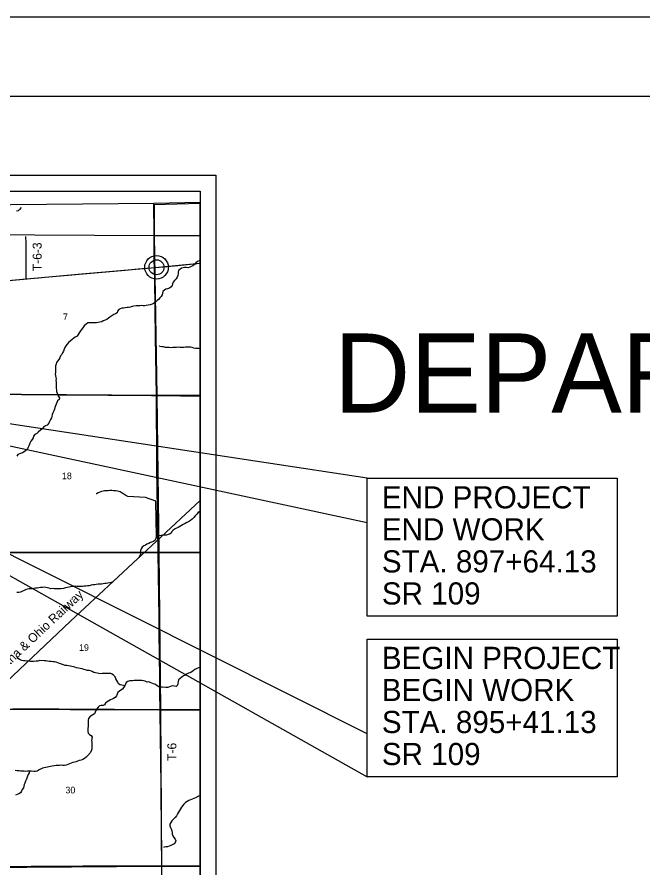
# Model space of a CAD drawing. Extents: x 0 to 34, y 0 to 22.
# Drawn here: x 7.74 to 11.7, y 16.62 to 22 of the extents above; entities that cross this region are included whole.
import ezdxf

# ---------------------------------------------------------------- set-up
doc = ezdxf.new("R2010")
doc.units = 0
for name, color, linetype in [('Default', 7, 'Continuous'), ('GM_X_County_Road', 7, 'Continuous'), ('GM_X_Minor_River', 7, 'Continuous'), ('GM_X_Rail_Line', 7, 'Continuous'), ('GM_X_Rail_Line_Text', 7, 'Continuous'), ('GM_X_Section', 7, 'Continuous'), ('GM_X_Section_Text', 7, 'Continuous'), ('GM_X_State_Route', 7, 'Continuous'), ('GM_X_Township_Road', 7, 'Continuous'), ('GM_X_Township_Road_Text', 7, 'Continuous'), ('GM_X_Unincorporated', 7, 'Continuous'), ('GM_X_Unincorporated_Location', 7, 'Continuous'), ('GM_X_US_Route', 7, 'Continuous'), ('SH_Border', 7, 'Continuous'), ('SH_Cut_Line', 7, 'Continuous'), ('SH_Data', 7, 'Continuous'), ('SH_Text', 7, 'Continuous')]:
    doc.layers.add(name, color=color, linetype=linetype)

msp = doc.modelspace()

# ---------------------------------------------------------------- linework, layer by layer
at = {"layer": 'Default'}
for points in [[(7.6731, 16.6285), (7.8317, 16.6301), (7.9032, 16.6305), (7.9964, 16.6311), (8.0835, 16.6316), (8.1582, 16.6322), (8.295, 16.6324), (8.3852, 16.6328), (8.438, 16.6333), (8.4971, 16.6335), (8.6215, 16.6337), (8.659, 16.6337), (8.7801, 16.6339), (8.9, 16.6342), (8.9, 20.8277), (8.6079, 20.8216), (7.476, 20.811)], [(7.5225, 14.1), (8.9, 14.1), (8.9, 16.6342), (8.7801, 16.6339), (8.659, 16.6337), (8.6215, 16.6337), (8.4971, 16.6335), (8.438, 16.6333), (8.3852, 16.6328), (8.295, 16.6324), (8.1582, 16.6322), (8.0835, 16.6316), (7.9964, 16.6311), (7.9032, 16.6305), (7.8317, 16.6301), (7.6731, 16.6285)]]:
    msp.add_lwpolyline(points, dxfattribs=at)
for points in [[(8.9, 20.618), (8.9, 20.8219), (8.6093, 20.8138), (8.611, 20.6193)], [(8.9, 19.6068), (8.9, 20.618), (8.611, 20.6193), (8.626, 19.6083)], [(8.9, 18.6163), (8.9, 19.6068), (8.626, 19.6083), (8.6395, 18.6159)], [(8.9, 17.622), (8.9, 18.6163), (8.6395, 18.6159), (8.6491, 17.6213)], [(8.9, 16.634), (8.9, 17.622), (8.6491, 17.6213), (8.6573, 16.6339)], [(8.9, 15.6272), (8.9, 16.634), (8.6573, 16.6339), (8.6614, 15.6262)]]:
    msp.add_lwpolyline(points, close=True, dxfattribs=at)
at = {"layer": 'GM_X_County_Road'}
for points in [[(7.4828, 19.6185), (7.4963, 19.6184), (7.5305, 19.6182), (7.7233, 19.6156), (8.0063, 19.6119), (8.056, 19.6111), (8.3201, 19.6098), (8.5938, 19.6077), (8.624, 19.6074)], [(8.624, 19.6074), (8.7772, 19.6056), (8.9, 19.6044)], [(7.4927, 18.6157), (7.5027, 18.6158), (7.5276, 18.6159), (7.935, 18.6156), (8.1215, 18.6157), (8.2739, 18.615), (8.5444, 18.6148), (8.6355, 18.6158)], [(8.6355, 18.6158), (8.6502, 18.6159), (8.9, 18.6177)], [(7.5136, 16.6249), (7.5156, 16.6255), (7.5177, 16.626), (7.5199, 16.6263), (7.5219, 16.6265), (7.5235, 16.6265), (7.5365, 16.6268), (7.5769, 16.6271), (7.6733, 16.628), (7.8319, 16.6295), (7.9034, 16.63), (7.9967, 16.6306), (8.0838, 16.6311), (8.1584, 16.6316), (8.2952, 16.6318), (8.3854, 16.6323), (8.4383, 16.6327), (8.4973, 16.6329), (8.6217, 16.6331), (8.6592, 16.6332)], [(8.6592, 16.6332), (8.7803, 16.6333), (8.9, 16.6336)]]:
    msp.add_lwpolyline(points, dxfattribs=at)
at = {"layer": 'GM_X_Minor_River'}
for points in [[(7.77, 20.7966), (7.7587, 20.7831), (7.7491, 20.776), (7.7396, 20.7719)], [(8.9, 20.4604), (8.8936, 20.4582), (8.8841, 20.4545), (8.8734, 20.4467), (8.8649, 20.4365), (8.8542, 20.4272), (8.8447, 20.4223), (8.8352, 20.419), (8.8253, 20.4149), (8.8124, 20.4162), (8.8026, 20.4171), (8.793, 20.4138), (8.7832, 20.4116), (8.7725, 20.4045), (8.7629, 20.3974), (8.7609, 20.3875), (8.7608, 20.3781), (8.7587, 20.3667), (8.7548, 20.3561), (8.7501, 20.3459), (8.739, 20.3347), (8.7305, 20.3238), (8.7262, 20.3139), (8.7238, 20.3034), (8.718, 20.2936), (8.7061, 20.2853), (8.6947, 20.2817), (8.6845, 20.2791), (8.6745, 20.2739), (8.6646, 20.2653), (8.6626, 20.2551), (8.6602, 20.2448), (8.6547, 20.2343), (8.6466, 20.2245), (8.6382, 20.2147), (8.6282, 20.2073), (8.6179, 20.1979), (8.6068, 20.1893), (8.5969, 20.1841), (8.5843, 20.18), (8.5729, 20.1782), (8.5604, 20.1757), (8.5509, 20.1747), (8.5407, 20.1744), (8.5308, 20.1757), (8.5187, 20.1754), (8.5073, 20.1755), (8.4952, 20.1738), (8.4815, 20.1716), (8.4712, 20.1695), (8.4587, 20.1662), (8.4488, 20.164), (8.439, 20.1633), (8.4287, 20.1623), (8.4166, 20.1602), (8.4063, 20.1588), (8.3961, 20.1562), (8.3858, 20.1521), (8.3773, 20.1412), (8.376, 20.1306), (8.3646, 20.1243), (8.3547, 20.1198), (8.3424, 20.1124), (8.3306, 20.103), (8.3206, 20.0963), (8.3099, 20.0881), (8.2993, 20.0836), (8.2886, 20.0788), (8.2783, 20.0736), (8.2665, 20.0715), (8.2566, 20.0682), (8.246, 20.0675), (8.2331, 20.0665), (8.2229, 20.0662), (8.2127, 20.0671), (8.2013, 20.0672), (8.1903, 20.0666), (8.1807, 20.0587), (8.1684, 20.0471), (8.1592, 20.0362), (8.1504, 20.026), (8.1434, 20.0155), (8.1357, 20.0046), (8.1299, 19.9944), (8.1229, 19.9838), (8.1107, 19.9756), (8.1012, 19.9708), (8.0905, 19.9625), (8.079, 19.9513), (8.0686, 19.9438)], [(8.0686, 19.9438), (8.059, 19.9322), (8.0524, 19.9224), (8.0447, 19.9111), (8.0412, 19.8997), (8.0361, 19.8884), (8.0307, 19.8774), (8.0271, 19.8676), (8.0183, 19.8575), (8.0132, 19.8461), (8.0063, 19.8356), (7.9997, 19.8258), (7.9928, 19.816), (7.99, 19.8054), (7.9864, 19.7948), (7.9863, 19.7835), (7.9854, 19.7736), (7.986, 19.763), (7.9851, 19.7524), (7.9839, 19.7425), (7.9864, 19.7319), (7.9889, 19.722), (7.99, 19.7125), (7.9891, 19.7022), (7.9897, 19.6924), (7.99, 19.6821), (7.991, 19.6723), (7.9907, 19.6525), (7.9925, 19.6427), (7.9935, 19.6324), (7.996, 19.6229), (8.0008, 19.6134), (8.0038, 19.6031), (8.0105, 19.5931), (8.0096, 19.5833), (7.9996, 19.5732), (7.9945, 19.563), (7.986, 19.5426), (7.9824, 19.5312), (7.9804, 19.5214), (7.9761, 19.5104), (7.9695, 19.4984), (7.9652, 19.4878), (7.9632, 19.476), (7.9608, 19.4662), (7.9542, 19.4553), (7.9484, 19.4428), (7.944, 19.4319), (7.9326, 19.4213), (7.923, 19.4161), (7.9108, 19.4083), (7.9035, 19.3978), (7.8931, 19.3899), (7.8771, 19.3764), (7.8675, 19.3682), (7.8557, 19.3615), (7.8461, 19.3509), (7.844, 19.3407), (7.8386, 19.3305), (7.8297, 19.3185), (7.8228, 19.306), (7.8204, 19.2947), (7.8134, 19.2822), (7.8083, 19.2705), (7.7968, 19.2589), (7.7873, 19.2518), (7.7773, 19.245), (7.7575, 19.2384), (7.7473, 19.2347), (7.7407, 19.2234)], [(8.9, 19.9028), (8.892, 19.9041), (8.8814, 19.9046), (8.8704, 19.9058), (8.8605, 19.907), (8.8496, 19.9102), (8.8394, 19.913), (8.8292, 19.9138), (8.8189, 19.9136), (8.8091, 19.9125), (8.7969, 19.9115), (8.7844, 19.9113), (8.7749, 19.911), (8.7617, 19.9123), (8.7503, 19.912), (8.7393, 19.911), (8.7276, 19.9103), (8.7177, 19.9085), (8.7045, 19.9106), (8.692, 19.9103), (8.681, 19.912), (8.6693, 19.9147), (8.6594, 19.9156), (8.6458, 19.9184), (8.6428, 19.9211)], [(8.4428, 18.9702), (8.4304, 18.9756), (8.4191, 18.9834), (8.4082, 18.9907), (8.3951, 18.9992), (8.3788, 19.0035), (8.3667, 19.0052), (8.3535, 19.006), (8.3428, 19.0065), (8.3292, 19.0067), (8.319, 19.0053), (8.308, 19.005), (8.2966, 19.0044), (8.2871, 19.0026), (8.2772, 19.0019), (8.2662, 18.9971), (8.2555, 18.9923), (8.2452, 18.9867), (8.2441, 18.9867)], [(8.6251, 18.7145), (8.6212, 18.94), (8.5549, 18.963), (8.4428, 18.9702)], [(8.9, 18.8761), (8.8983, 18.8748), (8.8887, 18.868), (8.8792, 18.8586), (8.8692, 18.8477), (8.8607, 18.8376), (8.8496, 18.8259), (8.8396, 18.8169), (8.8282, 18.8102), (8.8164, 18.8058), (8.8064, 18.7983), (8.7939, 18.7928), (8.7839, 18.7864), (8.7721, 18.7793), (8.7626, 18.7741), (8.7515, 18.7693), (8.742, 18.7652), (8.7309, 18.7574), (8.7209, 18.7472), (8.7166, 18.737), (8.7071, 18.7322), (8.6976, 18.7285), (8.6877, 18.7256), (8.6763, 18.7246), (8.6657, 18.7247), (8.6551, 18.7233), (8.6445, 18.7207), (8.635, 18.7189), (8.6251, 18.7145), (8.6196, 18.7043), (8.6161, 18.6937), (8.6058, 18.6851), (8.586, 18.6777), (8.5753, 18.6733), (8.5643, 18.6681), (8.5547, 18.6628), (8.5448, 18.6573), (8.5348, 18.6486), (8.5271, 18.6381), (8.5236, 18.6275), (8.5212, 18.6165), (8.5226, 18.6051), (8.5198, 18.5949), (8.5136, 18.5836), (8.5094, 18.5795)], [(8.5094, 18.5795), (8.3492, 18.4305)], [(8.3492, 18.4305), (8.3389, 18.4253), (8.3275, 18.4239), (8.318, 18.4213), (8.307, 18.4203), (8.2972, 18.4189), (8.2877, 18.4171), (8.2774, 18.4161), (8.2668, 18.4151), (8.2551, 18.4152), (8.2425, 18.4138), (8.2323, 18.4116), (8.2224, 18.4102), (8.211, 18.4084), (8.1992, 18.4048), (8.1875, 18.4053), (8.1776, 18.4031), (8.1678, 18.4024), (8.1579, 18.401), (8.1465, 18.4004), (8.1332, 18.4005), (8.123, 18.401), (8.1128, 18.4019), (8.1014, 18.4016), (8.0908, 18.4006), (8.0813, 18.3992), (8.0718, 18.3955), (8.06, 18.3937), (8.0486, 18.3919), (8.0368, 18.3871), (8.0228, 18.3865), (8.0107, 18.3855), (7.9997, 18.3867), (7.9902, 18.3857), (7.9777, 18.3858), (7.9675, 18.3875), (7.9565, 18.3868), (7.9467, 18.3892), (7.9353, 18.3916), (7.9244, 18.3944), (7.9146, 18.3956), (7.9043, 18.3942), (7.8922, 18.3939), (7.8808, 18.3918), (7.8698, 18.3911), (7.8595, 18.3897), (7.8489, 18.3872), (7.8383, 18.3869), (7.8284, 18.3859), (7.8182, 18.3852), (7.806, 18.3835), (7.7958, 18.379), (7.7839, 18.3734), (7.7733, 18.3686), (7.7638, 18.3649), (7.7539, 18.3624), (7.7414, 18.3621)], [(8.4241, 17.7722), (8.4158, 17.7742), (8.4056, 17.7766), (8.3951, 17.7801), (8.3853, 17.7855), (8.3801, 17.7962), (8.3742, 17.8069), (8.3671, 17.818), (8.3631, 17.8286), (8.3552, 17.8386), (8.3455, 17.8467), (8.3357, 17.8498), (8.3239, 17.8503), (8.3137, 17.85), (8.3023, 17.8501), (8.291, 17.8503), (8.2811, 17.8504), (8.2709, 17.8482), (8.2599, 17.8513), (8.2497, 17.8526), (8.2391, 17.8542), (8.2293, 17.8574), (8.2184, 17.8635), (8.2078, 17.8674), (8.198, 17.8694), (8.1874, 17.8696), (8.1761, 17.8731), (8.1651, 17.8755), (8.1542, 17.8794), (8.1425, 17.8814), (8.1307, 17.8846), (8.1198, 17.8866), (8.1092, 17.8912), (8.099, 17.8936), (8.079, 17.8972), (8.0677, 17.8993), (8.0578, 17.9009), (8.0476, 17.9014), (8.0363, 17.9049), (8.0246, 17.9107), (8.0121, 17.9146), (8.0012, 17.9189), (7.9906, 17.9213), (7.9804, 17.9237), (7.9687, 17.9253), (7.9589, 17.9262), (7.9456, 17.9271), (7.9354, 17.928), (7.9252, 17.93), (7.9138, 17.9316), (7.8869, 17.9319), (7.8744, 17.9294), (7.8638, 17.9283), (7.8475, 17.9274), (7.8372, 17.9267), (7.827, 17.9272), (7.8164, 17.9281), (7.8043, 17.9297), (7.7941, 17.9302), (7.7835, 17.9299), (7.7729, 17.9338), (7.7627, 17.9377), (7.7514, 17.9424), (7.7409, 17.9505)], [(8.9, 17.8912), (8.8897, 17.8873), (8.8802, 17.8824), (8.868, 17.875), (8.8577, 17.8682), (8.8473, 17.8604), (8.837, 17.8552), (8.8268, 17.8526), (8.8142, 17.8456), (8.8046, 17.8385), (8.7951, 17.8363), (8.7848, 17.8265), (8.7752, 17.8187), (8.7649, 17.81), (8.7613, 17.7994), (8.7604, 17.7877), (8.7584, 17.7775), (8.7496, 17.7677), (8.7378, 17.7697), (8.7269, 17.7725), (8.717, 17.7707), (8.7063, 17.7655), (8.6961, 17.7622)], [(8.6961, 17.7622), (8.6847, 17.7619), (8.6635, 17.7637), (8.6514, 17.7642), (8.6393, 17.7654), (8.6288, 17.7735), (8.619, 17.7805), (8.6066, 17.7859), (8.5956, 17.7894), (8.5858, 17.7941), (8.576, 17.7976), (8.5665, 17.7969), (8.5537, 17.8028), (8.5424, 17.804), (8.5314, 17.806), (8.5174, 17.8073), (8.5064, 17.8074), (8.4958, 17.8068), (8.4844, 17.8073), (8.4738, 17.8051), (8.4632, 17.8048), (8.4537, 17.8042), (8.4435, 17.8012), (8.4339, 17.793), (8.4284, 17.7824), (8.4241, 17.7722), (8.4168, 17.7621), (8.4095, 17.7523), (8.3996, 17.7448), (8.39, 17.7396), (8.38, 17.7298), (8.3757, 17.7193), (8.3718, 17.7094), (8.3634, 17.6993), (8.3538, 17.6929), (8.3435, 17.6889), (8.3329, 17.684), (8.3226, 17.6785), (8.3126, 17.6717), (8.3031, 17.6631), (8.2969, 17.6522), (8.2866, 17.6489), (8.2756, 17.6475), (8.2653, 17.6468), (8.255, 17.6386), (8.2465, 17.6273), (8.2403, 17.6171), (8.2376, 17.6069), (8.2325, 17.5963), (8.2126, 17.5829), (8.2023, 17.5773), (8.1958, 17.5667), (8.193, 17.5562), (8.1925, 17.5452), (8.1923, 17.5353), (8.1926, 17.5247), (8.1921, 17.5148), (8.1904, 17.5042), (8.1903, 17.4936), (8.1906, 17.4841), (8.1923, 17.4738), (8.2005, 17.4643), (8.2126, 17.4592), (8.2174, 17.4493), (8.2165, 17.4379), (8.2148, 17.4262), (8.2158, 17.4159), (8.2165, 17.4053), (8.2163, 17.3939), (8.2166, 17.3837), (8.2149, 17.3731), (8.2125, 17.3617), (8.2071, 17.3515), (8.1902, 17.332), (8.1794, 17.3226), (8.1691, 17.314), (8.1584, 17.3077), (8.1481, 17.3032), (8.1367, 17.2999), (8.1257, 17.2966), (8.1158, 17.2933), (8.1063, 17.2904), (8.0952, 17.2875), (8.0846, 17.2838), (8.0743, 17.2793), (8.0644, 17.2749), (8.0545, 17.272), (8.0435, 17.2702), (8.0333, 17.2695), (8.023, 17.2704), (8.012, 17.2697), (8.001, 17.2695), (7.9893, 17.2692), (7.9779, 17.2671), (7.9661, 17.2657), (7.9544, 17.2635), (7.9445, 17.2617), (7.935, 17.2592), (7.9251, 17.2562), (7.9141, 17.2541), (7.9042, 17.2515)], [(7.9042, 17.2515), (7.8947, 17.2478), (7.8825, 17.2415), (7.871, 17.2329), (7.8592, 17.2319), (7.849, 17.2312), (7.8327, 17.2333), (7.8221, 17.2338), (7.8092, 17.2324), (7.7986, 17.2318), (7.7876, 17.233), (7.7755, 17.2339), (7.7657, 17.234), (7.7555, 17.2356), (7.7445, 17.2361), (7.7316, 17.237)], [(7.8221, 17.2338), (7.819, 17.2228), (7.8139, 17.2123), (7.8096, 17.2013), (7.8053, 17.1896), (7.801, 17.1794), (7.7963, 17.1696), (7.7916, 17.1586), (7.7881, 17.1488), (7.7868, 17.1378), (7.7833, 17.1276), (7.7763, 17.1171), (7.7716, 17.1061), (7.7643, 17.0963), (7.7544, 17.0896), (7.7441, 17.0852), (7.7342, 17.0811)], [(8.9, 17.0785), (8.8997, 17.0784), (8.8902, 17.0747), (8.8704, 17.0658), (8.8601, 17.0606), (8.8501, 17.0554), (8.8399, 17.0521), (8.8292, 17.0473), (8.8185, 17.0409), (8.8082, 17.0346), (8.7986, 17.0252), (8.7832, 17.0056), (8.7774, 16.9951), (8.7708, 16.9845), (8.7639, 16.974), (8.7573, 16.9627), (8.7522, 16.9513), (8.7426, 16.9404), (8.7326, 16.9303), (8.7223, 16.9202), (8.7161, 16.9096), (8.7091, 16.8983), (8.7093, 16.8877), (8.7126, 16.8774), (8.7167, 16.8679), (8.7222, 16.8564), (8.7232, 16.8458), (8.7234, 16.8348), (8.7286, 16.8237), (8.7353, 16.8142), (8.7424, 16.8035), (8.7475, 16.7932), (8.7425, 16.7834), (8.7356, 16.7736), (8.7157, 16.764), (8.7051, 16.7599), (8.694, 16.7562), (8.6838, 16.7548), (8.6735, 16.753), (8.6701, 16.7519)]]:
    msp.add_lwpolyline(points, dxfattribs=at)
at = {"layer": 'GM_X_Rail_Line'}
for points in [[(2.1, 19.6449), (2.4687, 19.6463), (3.2362, 19.6474), (3.7244, 19.6491), (5.0197, 19.6574), (5.4852, 19.6574), (5.5146, 19.6675), (5.5588, 19.7034), (6.1514, 20.0969), (6.291, 20.193), (6.3333, 20.2132), (6.3747, 20.2169), (6.4833, 20.2279), (7.4795, 20.3149), (8.1518, 20.3773), (8.7379, 20.4271), (8.9, 20.4441)], [(5.6036, 14.1), (5.6231, 15.2124), (5.6254, 15.4429), (5.6392, 15.5731), (5.6554, 15.6619), (5.6784, 15.7322), (5.7095, 15.8198), (5.7429, 15.8889), (5.7752, 15.9442), (5.8121, 16.0007), (5.8512, 16.0606), (5.9042, 16.1217), (5.9987, 16.2174), (6.5299, 16.7153), (7.3509, 17.4922), (8.0819, 18.1807), (8.7161, 18.7707), (8.9, 18.9438)]]:
    msp.add_lwpolyline(points, dxfattribs=at)
at = {"layer": 'GM_X_Section'}
for points in [[(7.4769, 20.6134), (7.4767, 20.6252), (8.611, 20.6193), (8.626, 19.6083), (7.4843, 19.6166)], [(7.4843, 19.6166), (8.626, 19.6083), (8.6395, 18.6159), (7.4927, 18.6151), (7.4844, 19.6018)], [(7.4927, 18.6151), (8.6395, 18.6159), (8.6491, 17.6213), (7.5039, 17.6243), (7.4929, 18.6076)], [(7.5039, 17.6243), (8.6491, 17.6213), (8.6573, 16.6339), (7.5172, 16.6244), (7.5038, 17.6183)], [(7.5172, 16.6244), (8.6573, 16.6339), (8.6614, 15.6262), (7.5223, 15.6321), (7.5171, 16.6191)]]:
    msp.add_lwpolyline(points, close=True, dxfattribs=at)
at = {"layer": 'GM_X_State_Route'}
msp.add_lwpolyline([(7.4782, 20.3161), (7.4846, 20.3167), (7.5559, 20.323), (7.6178, 20.3286), (7.7324, 20.3388), (7.8006, 20.3449), (7.878, 20.3519), (7.9647, 20.3593), (8.0174, 20.364), (8.067, 20.3682), (8.1351, 20.3744), (8.259, 20.3854), (8.3055, 20.3899), (8.4262, 20.401), (8.5099, 20.4087), (8.5904, 20.4154), (8.6122, 20.4173), (8.6173, 20.4178), (8.7876, 20.4331), (8.8557, 20.4398), (8.9, 20.4439)], dxfattribs=at)
at = {"layer": 'GM_X_Township_Road'}
for points in [[(8.6122, 20.4173), (8.611, 20.4563), (8.6103, 20.5961), (8.6099, 20.6614), (8.6081, 20.7889), (8.6081, 20.821)], [(7.8006, 20.3449), (7.8006, 20.3474), (7.8, 20.3784), (7.7999, 20.4101), (7.8, 20.4269), (7.8, 20.4505), (7.7998, 20.4877), (7.7998, 20.5325), (7.7998, 20.5523), (7.7996, 20.5697), (7.7997, 20.5884), (7.7995, 20.5964), (7.7987, 20.6088), (7.7989, 20.6119)], [(8.624, 19.6074), (8.6202, 19.8595), (8.6187, 19.9714), (8.6137, 20.3413), (8.6122, 20.4158), (8.6122, 20.4173)], [(8.6355, 18.6158), (8.6347, 18.6597), (8.6322, 18.812), (8.6313, 18.8897), (8.6289, 19.014), (8.627, 19.1446), (8.6261, 19.2534), (8.6244, 19.5331), (8.624, 19.6046), (8.624, 19.6074)], [(8.6476, 17.6224), (8.6463, 17.7272), (8.6452, 17.8204), (8.6421, 18.1126), (8.6411, 18.2027), (8.6355, 18.613), (8.6355, 18.6158)], [(8.6592, 16.6332), (8.6593, 16.6392), (8.6571, 16.8195), (8.6537, 17.149), (8.6516, 17.2951), (8.6477, 17.609), (8.6476, 17.6224)], [(8.6601, 15.6282), (8.66, 15.6352), (8.6601, 15.7906), (8.6601, 15.943), (8.6597, 16.2165), (8.6595, 16.3999), (8.6592, 16.6332)]]:
    msp.add_lwpolyline(points, dxfattribs=at)
at = {"layer": 'GM_X_Unincorporated'}
for radius in [0.0744, 0.0472]:
    msp.add_circle((8.6249, 20.4181), radius, dxfattribs=at)
at = {"layer": 'GM_X_Unincorporated_Location'}
msp.add_line((8.6249, 20.4181), (8.6249, 20.4181), dxfattribs=at)
at = {"layer": 'GM_X_US_Route'}
msp.add_lwpolyline([(7.7155, 17.628), (7.7807, 17.6276), (7.818, 17.6276), (7.8614, 17.6271), (8.0074, 17.6265), (8.054, 17.6263), (8.113, 17.6259), (8.2123, 17.6255), (8.321, 17.6246), (8.3583, 17.6243), (8.3893, 17.6239), (8.439, 17.6239), (8.4636, 17.6237), (8.4845, 17.6235), (8.5442, 17.6228), (8.6476, 17.6224), (8.7496, 17.622), (8.7598, 17.6222), (8.7899, 17.6221), (8.8366, 17.622), (8.8988, 17.6218), (8.9, 17.6218)], dxfattribs=at)
at = {"layer": 'SH_Border'}
msp.add_lwpolyline([(1.5, 21.5), (33.5, 21.5), (33.5, 0.5), (1.5, 0.5)], close=True, dxfattribs=at)
at = {"layer": 'SH_Cut_Line'}
for points in [[(0, 0), (34, 0), (34, 22), (0, 22)], [(2.1, 20.6957), (2.1, 14.1), (8.9, 14.1), (8.9, 20.8277), (8.6079, 20.8216), (7.476, 20.811), (6.4789, 20.8005), (5.4741, 20.7803), (4.4698, 20.7584), (3.7151, 20.7343), (2.4566, 20.7022)]]:
    msp.add_lwpolyline(points, close=True, dxfattribs=at)
at = {"layer": 'SH_Data'}
for p, q in [((2, 21), (9, 21)), ((9, 21), (9, 14)), ((2.1, 20.9), (8.9, 20.9)), ((8.9, 20.9), (8.9, 14.1))]:
    msp.add_line(p, q, dxfattribs=at)
at = {"layer": 'SH_Text'}
for points in [[(5.4846, 19.763), (9.956, 18.8047), (9.956, 19.0851)], [(5.4846, 19.7138), (9.956, 17.197), (9.956, 17.4693)], [(9.956, 19.0851), (11.537, 19.0851), (11.537, 18.2141), (9.956, 18.2141)], [(9.956, 18.068), (11.537, 18.068), (11.537, 17.197), (9.956, 17.197)]]:
    msp.add_lwpolyline(points, close=True, dxfattribs=at)

# ---------------------------------------------------------------- texts
at = {"layer": 'GM_X_Rail_Line_Text'}
msp.add_text('Indiana & Ohio Railway', height=0.056629, rotation=43.1881, dxfattribs=at).set_placement((7.5929, 17.8042))
at = {"layer": 'GM_X_Section_Text'}
for s, height, p in [('7', 0.0419, (8.0333, 20.0843)), ('18', 0.04186, (8.0271, 19.0788)), ('19', 0.04186, (8.135, 17.9938)), ('30', 0.04186, (8.0492, 17.093))]:
    msp.add_text(s, height=height, rotation=0, dxfattribs=at).set_placement(p)
at = {"layer": 'GM_X_Township_Road_Text'}
for s, rotation, p in [('T-6-3', 90, (7.8986, 20.3937)), ('T-6', 90.4772, (8.7511, 17.2987))]:
    msp.add_text(s, height=0.05682, rotation=rotation, dxfattribs=at).set_placement(p)
at = {"layer": 'SH_Text'}
for s, height, p in [('DEPARTMENT OF TRANSPORTATION', 0.5, (9.7466, 19.5)), ('END PROJECT', 0.14, (10.0498, 18.8943)), ('END WORK', 0.14, (10.0498, 18.6918)), ('STA. 897+64.13', 0.14, (10.0498, 18.4893)), ('SR 109', 0.14, (10.0498, 18.2868)), ('BEGIN PROJECT', 0.14, (10.0498, 17.8793)), ('BEGIN WORK', 0.14, (10.0498, 17.6768)), ('STA. 895+41.13', 0.14, (10.0498, 17.4743)), ('SR 109', 0.14, (10.0498, 17.2718))]:
    msp.add_text(s, height=height, dxfattribs=at).set_placement(p)

doc.saveas('drawing.dxf')
